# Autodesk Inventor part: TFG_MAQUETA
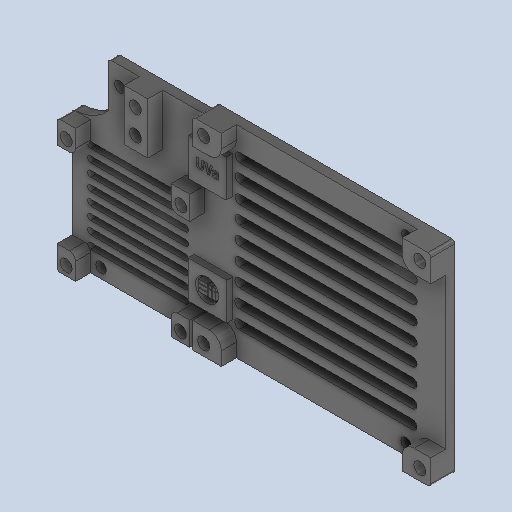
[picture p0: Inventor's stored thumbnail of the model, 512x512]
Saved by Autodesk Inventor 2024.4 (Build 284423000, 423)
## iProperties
Created: 2025-06
Part Number: TFG_MAQUETA
Material: Generic
Document SubType Name: Modeling
Designer: AdminForWorker
Density: 1 g/cm^3
Appearance: Default
Title: SOPORTE MODULOS v2
Author: AdminForWorker
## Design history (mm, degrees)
feature "SOPORTE DE MÓDULOS"
body "Solid1"
